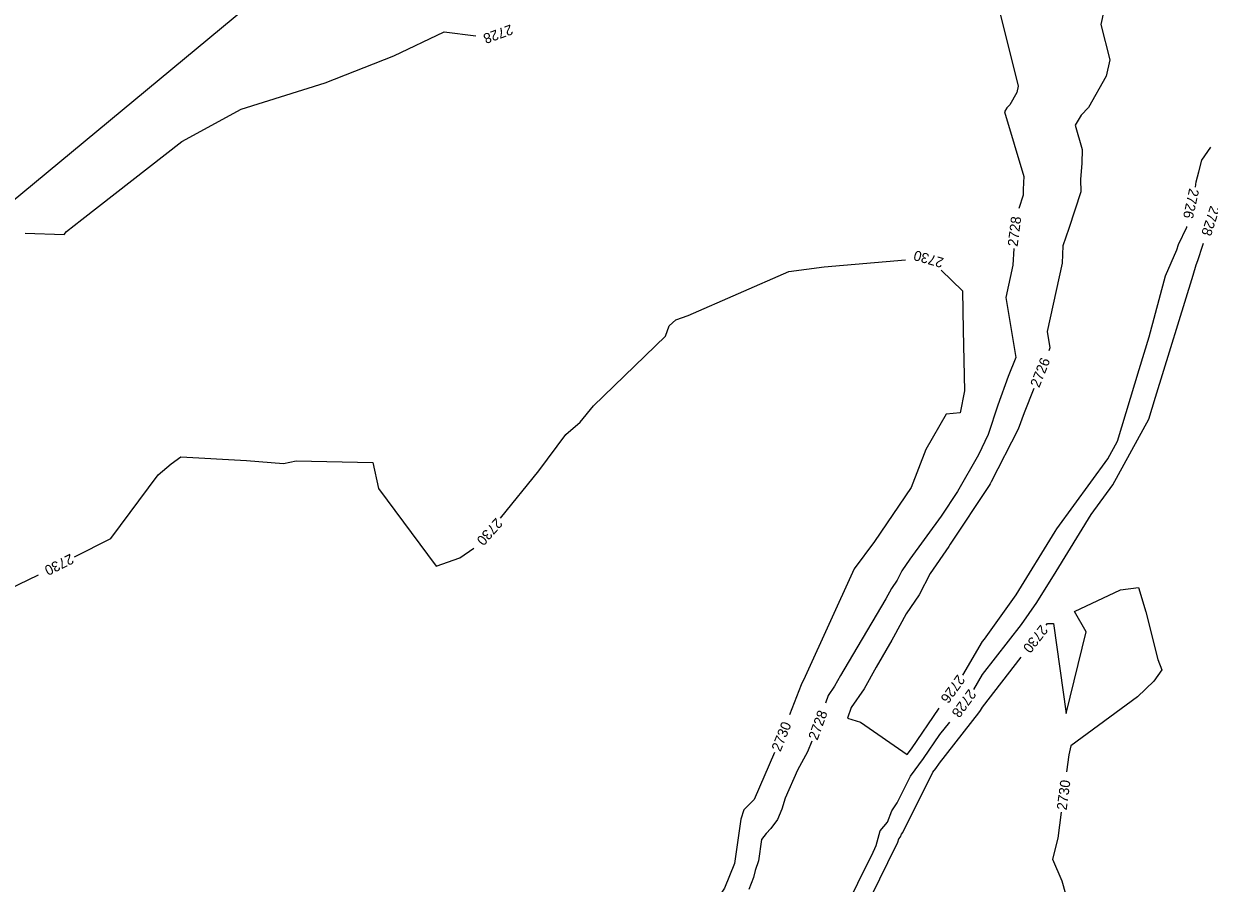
# Model space of a CAD drawing. Extents: x 1326424 to 1329294, y 1001359 to 1003823.
# Drawn here: x 1327755.7 to 1327989.8, y 1002687.1 to 1002856.6 of the extents above; entities that cross this region are included whole.
import ezdxf

# ---------------------------------------------------------------- set-up
doc = ezdxf.new("R2010")
doc.units = 0
doc.layers.add('Prop SS Transition Line', color=7, linetype='Continuous')
doc.layers.add('Scratch_Level_3', color=7, linetype='Continuous')

msp = doc.modelspace()

# ---------------------------------------------------------------- linework, layer by layer
at = {"layer": 'Prop SS Transition Line'}
msp.add_line((1327952.45, 1002986.45), (1327671.95, 1002754.06), dxfattribs=at)
at = {"layer": 'Scratch_Level_3'}
for points in [[(1327964.39, 1002889.79), (1327976.27, 1002886.01), (1327948.4, 1002875.99), (1327947.88, 1002867.23), (1327948.01, 1002866.24), (1327947.96, 1002865.29), (1327947.81, 1002864.45), (1327947.48, 1002862.9), (1327952.1, 1002844.34), (1327951.84, 1002843.07), (1327950.45, 1002840.62), (1327949.87, 1002840.03), (1327949.39, 1002839.25), (1327953.18, 1002826.51), (1327953.15, 1002825.3), (1327953.04, 1002823.91), (1327953.06, 1002822.83), (1327952.18, 1002820.17)], [(1327980.01, 1002881.13), (1327980.19, 1002880.1), (1327980.48, 1002877.13), (1327969.88, 1002873.32), (1327969.68, 1002870.03), (1327970.08, 1002866.94), (1327969.92, 1002863.97), (1327969.46, 1002861.34), (1327968.43, 1002856.47), (1327970.16, 1002849.51), (1327969.48, 1002846.31), (1327965.99, 1002840.11), (1327964.52, 1002838.61), (1327963.3, 1002836.63), (1327964.72, 1002831.85), (1327964.65, 1002829.11), (1327964.4, 1002825.94), (1327964.45, 1002823.48), (1327962.06, 1002816.28), (1327960.92, 1002812.86), (1327960.74, 1002809.43), (1327957.82, 1002795.9), (1327958.35, 1002792.72), (1327958.11, 1002792.14)], [(1327755.99, 1002815.36), (1327763.74, 1002815.06), (1327764.18, 1002815.63), (1327767.2, 1002818.04), (1327786.95, 1002833.44), (1327798.69, 1002839.81), (1327815.26, 1002845), (1327828.78, 1002850.29), (1327838.76, 1002855.05), (1327845.03, 1002854.27)], [(1327987.09, 1002824.41), (1327987.23, 1002825.43), (1327987.74, 1002827.43), (1327988.33, 1002829.71), (1327990.12, 1002832.28)], [(1327941.16, 1002728.14), (1327945.04, 1002734.77), (1327945.41, 1002735.25), (1327951.65, 1002743.97), (1327959.36, 1002756.44), (1327959.69, 1002756.99), (1327969.77, 1002770.8), (1327971.68, 1002774.28), (1327975.95, 1002788.43), (1327977.97, 1002794.9), (1327981.17, 1002806.89), (1327983.43, 1002812.04), (1327983.76, 1002813.09), (1327985.4, 1002816.49), (1327985.41, 1002816.64)], [(1327951.19, 1002812.29), (1327951.02, 1002809.02), (1327949.64, 1002802.63), (1327951.59, 1002790.77), (1327950.1, 1002787.03), (1327948.04, 1002781.37), (1327946.14, 1002775.58), (1327944.27, 1002771.62), (1327940.11, 1002764.37), (1327936.86, 1002759.48), (1327930.71, 1002751.01), (1327929.1, 1002748.69), (1327928.17, 1002746.86), (1327927.06, 1002745.2), (1327925.96, 1002743.21), (1327918.51, 1002730.64), (1327917.01, 1002728.03), (1327915.84, 1002725.95), (1327914.59, 1002724.13), (1327914.06, 1002722.63)], [(1327943.3, 1002725.33), (1327945.03, 1002728.28), (1327952.71, 1002738.14), (1327955.79, 1002742.44), (1327959.58, 1002748.58), (1327966.52, 1002759.84), (1327970.77, 1002765.66), (1327977.86, 1002778.64), (1327979.17, 1002782.96), (1327986.66, 1002807.05), (1327987.2, 1002809.07), (1327987.58, 1002809.93), (1327988.52, 1002812.97), (1327988.7, 1002813.33)], [(1327849.86, 1002759.08), (1327857.44, 1002768.47), (1327862.76, 1002775.58), (1327865.63, 1002778.01), (1327868.26, 1002781.26), (1327882.43, 1002795.04), (1327883.14, 1002797.05), (1327884.47, 1002798.2), (1327886.9, 1002799.1), (1327906.81, 1002807.74), (1327913.76, 1002808.68), (1327929.85, 1002810.04)], [(1327936.86, 1002808.05), (1327941.07, 1002803.98), (1327941.23, 1002796.16), (1327941.5, 1002784.24), (1327940.61, 1002779.9), (1327937.86, 1002779.63), (1327933.84, 1002772.63), (1327930.95, 1002765.15), (1327923.71, 1002754.49), (1327919.69, 1002749.1), (1327909.99, 1002727.86), (1327909.25, 1002726.24), (1327906.96, 1002720.3)], [(1327955.15, 1002784.71), (1327953.23, 1002779.9), (1327952.06, 1002776.68), (1327946.75, 1002766.25), (1327946.58, 1002765.89), (1327946.37, 1002765.54), (1327938.68, 1002753.94), (1327938.38, 1002753.53), (1327934.68, 1002748.2), (1327932.54, 1002744), (1327929.99, 1002740.21), (1327927.48, 1002735.65), (1327927.12, 1002735.04), (1327924.07, 1002729.69), (1327921.66, 1002725.45), (1327919.11, 1002721.74), (1327918.38, 1002719.67), (1327920.93, 1002718.83), (1327930.18, 1002712.47), (1327931, 1002713.58), (1327936.5, 1002721.64)], [(1327765.79, 1002751.47), (1327772.94, 1002755.11), (1327782.29, 1002767.63), (1327784.85, 1002769.84), (1327786.78, 1002771.21), (1327799.74, 1002770.46), (1327807.01, 1002769.89), (1327809.53, 1002770.39), (1327824.64, 1002770.06), (1327825.75, 1002764.98), (1327837.18, 1002749.6), (1327841.86, 1002751.3), (1327844.6, 1002753.16)], [(1327670.64, 1002708.17), (1327675.88, 1002710.86), (1327675.97, 1002710.94), (1327676.04, 1002711), (1327683.04, 1002718.39), (1327682.96, 1002719), (1327683.3, 1002718.91), (1327691.89, 1002720.72), (1327700.91, 1002724.22), (1327713.55, 1002724.5), (1327720.48, 1002731), (1327735.13, 1002735.55), (1327739.56, 1002736.87), (1327744.46, 1002738.81), (1327752.77, 1002745.12), (1327758.63, 1002747.91)], [(1327957.61, 1002737.96), (1327957.89, 1002738.32), (1327959.04, 1002738.35), (1327961.54, 1002720.55), (1327965.49, 1002736.68), (1327963.22, 1002740.69), (1327972.28, 1002744.96), (1327975.86, 1002745.39), (1327977.3, 1002740.65), (1327979.64, 1002731.2), (1327980.42, 1002729.18), (1327978.84, 1002726.96), (1327975.64, 1002723.83), (1327962.49, 1002714.16), (1327962.07, 1002712.38), (1327961.63, 1002709.03)], [(1327903.41, 1002645.16), (1327903.84, 1002646.31), (1327909.12, 1002655.87), (1327917.23, 1002672.75), (1327917.69, 1002673.61), (1327919.45, 1002676.88), (1327919.82, 1002677.51), (1327920.13, 1002678.55), (1327927.88, 1002694.26), (1327928.12, 1002694.72), (1327928.32, 1002695.17), (1327928.5, 1002695.83), (1327928.83, 1002696.22), (1327929.03, 1002696.74), (1327929.28, 1002697.11), (1327935.25, 1002708.97), (1327935.81, 1002709.73), (1327936.52, 1002710.78), (1327944.29, 1002720.67), (1327944.66, 1002721.18), (1327945.02, 1002721.8), (1327952.7, 1002731.65)], [(1327892.8, 1002630.49), (1327895.83, 1002638.63), (1327897.33, 1002642.68), (1327908.14, 1002662.27), (1327911.68, 1002669.62), (1327912.81, 1002671.7), (1327917.06, 1002679.6), (1327917.94, 1002681.14), (1327918.7, 1002683.63), (1327922.13, 1002690.59), (1327923.2, 1002692.59), (1327924.06, 1002694.54), (1327924.85, 1002697.4), (1327926.28, 1002699.1), (1327927.14, 1002701.33), (1327928.21, 1002702.94), (1327930.85, 1002708.19), (1327933.4, 1002711.66), (1327936.64, 1002716.4), (1327938.59, 1002718.88)], [(1327911.31, 1002715.12), (1327910.49, 1002712.97), (1327908.5, 1002709.36), (1327906.09, 1002703.88), (1327905.39, 1002701.71), (1327904.56, 1002699.67), (1327903.27, 1002697.88), (1327902.29, 1002696.87), (1327901.41, 1002695.73), (1327900.81, 1002691.49), (1327900.18, 1002689.61), (1327899.85, 1002688.2), (1327898.89, 1002685.81)], [(1327903.99, 1002712.88), (1327899.92, 1002703.62), (1327897.88, 1002701.53), (1327897.29, 1002699.69), (1327896.05, 1002690.99), (1327894.09, 1002686.08), (1327888.66, 1002678.04), (1327888.08, 1002676.28), (1327883.94, 1002667.39), (1327883.9, 1002667.26), (1327881.96, 1002662.16), (1327877.34, 1002651.7), (1327877.25, 1002651.52), (1327873.26, 1002637.63), (1327873.1, 1002637.2), (1327873.09, 1002637.06), (1327872.99, 1002636.78), (1327867.9, 1002627.53), (1327867.8, 1002627.41), (1327867.7, 1002627.31), (1327867.61, 1002627.22), (1327864.57, 1002622)], [(1327960.59, 1002701.1), (1327959.92, 1002695.99), (1327958.88, 1002691.85), (1327960.67, 1002687.57), (1327966.34, 1002667.49), (1327955.96, 1002649.77), (1327954.84, 1002647.61), (1327954.91, 1002646.71), (1327954.23, 1002645.25), (1327955.95, 1002639.71), (1327957.96, 1002637.5), (1327969.57, 1002644.95), (1327971.28, 1002655.57), (1327974.79, 1002650.4)]]:
    msp.add_lwpolyline(points, dxfattribs=at)

# ---------------------------------------------------------------- texts
for s, rotation, p in [('2728', 199.8845, (1327851.87, 1002856.54)), ('2726', 257.7587, (1327985.87, 1002824.27)), ('2728', 252.1608, (1327990.03, 1002820.86)), ('2728', 82.895, (1327951.96, 1002812.6)), ('2730', 164.2162, (1327937.52, 1002810.37)), ('2726', 68.2361, (1327956.23, 1002784.72)), ('2730', 228.3012, (1327848.97, 1002759.28)), ('2730', 206.4357, (1327764.96, 1002752.13)), ('2730', 232.0738, (1327956.55, 1002738.22)), ('2726', 234.3493, (1327940.12, 1002728.38)), ('2728', 233.8457, (1327942.34, 1002725.52)), ('2728', 69.91, (1327912.44, 1002715.15)), ('2730', 68.1964, (1327905.14, 1002712.9)), ('2730', 82.5302, (1327961.64, 1002701.41))]:
    msp.add_text(s, height=2, rotation=rotation, dxfattribs=at).set_placement(p)

doc.saveas('drawing.dxf')
